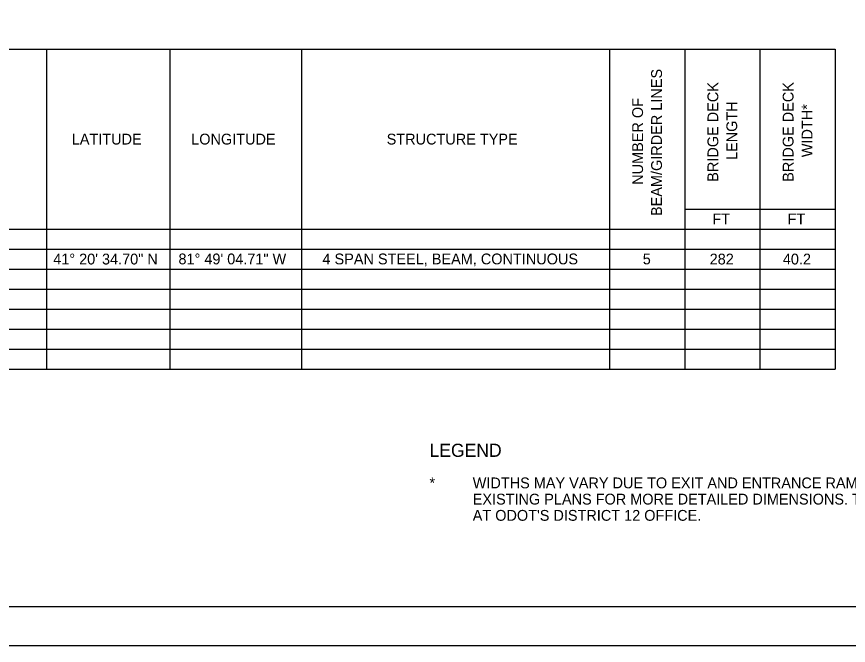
# Model space of a CAD drawing. Extents: x 0 to 680, y 0 to 440.
# Drawn here: x 339 to 554.3, y 0 to 162.7 of the extents above; entities that cross this region are included whole.
import ezdxf

# ---------------------------------------------------------------- set-up
doc = ezdxf.new("R2010")
doc.units = 0
for name, color, linetype in [('DR_P_Text', 7, 'Continuous'), ('SH_Border', 7, 'Continuous'), ('SH_Cut_Line', 7, 'Continuous'), ('SH_Text', 7, 'Continuous')]:
    doc.layers.add(name, color=color, linetype=linetype)

msp = doc.modelspace()

# ---------------------------------------------------------------- linework, layer by layer
at = {"layer": 'SH_Border'}
msp.add_lwpolyline([(30, 430), (670, 430), (670, 10), (30, 10)], close=True, dxfattribs=at)
at = {"layer": 'SH_Cut_Line'}
msp.add_lwpolyline([(0, 0), (680, 0), (680, 440), (0, 440)], close=True, dxfattribs=at)
at = {"layer": 'SH_Text'}
for p, q in [((124.85, 154.3), (550.93, 154.3)), ((346.72, 154.3), (346.72, 71.51)), ((378.67, 154.3), (378.67, 71.51)), ((412.76, 154.3), (412.76, 71.51)), ((492.5, 154.3), (492.5, 71.51)), ((511.98, 154.3), (511.98, 71.51)), ((531.46, 154.3), (531.46, 71.51)), ((550.93, 154.3), (550.93, 71.51)), ((511.98, 112.9), (550.93, 112.9)), ((124.85, 107.73), (550.93, 107.73)), ((124.85, 102.56), (550.93, 102.56)), ((124.85, 97.38), (550.93, 97.38)), ((124.85, 92.21), (550.93, 92.21)), ((124.85, 87.04), (550.93, 87.04)), ((124.85, 81.86), (550.93, 81.86)), ((124.85, 76.69), (550.93, 76.69)), ((124.85, 71.51), (550.93, 71.51))]:
    msp.add_line(p, q, dxfattribs=at)

# ---------------------------------------------------------------- texts
at = {"layer": 'DR_P_Text'}
for s, height, p in [('LEGEND', 3.4, (445.9, 48.78)), ('*', 2.8, (445.9, 40.64)), ('WIDTHS MAY VARY DUE TO EXIT AND ENTRANCE RAMPS ON THE STRUCTURE. SEE', 2.8, (457.1, 40.64)), ('EXISTING PLANS FOR MORE DETAILED DIMENSIONS. THESE PLANS CAN BE VIEWED', 2.8, (457.1, 36.44)), ("AT ODOT'S DISTRICT 12 OFFICE.", 2.8, (457.1, 32.24))]:
    msp.add_text(s, height=height, dxfattribs=at).set_placement(p)
at = {"layer": 'SH_Text'}
for s, p in [('BEAM/GIRDER LINES', (506.09, 111.11)), ('BRIDGE DECK ', (520.67, 119.97)), ('BRIDGE DECK ', (540.15, 119.97)), ('NUMBER OF ', (501.19, 119.18)), ('LENGTH', (525.57, 125.6)), ('WIDTH*', (545.05, 126.33))]:
    msp.add_text(s, height=2.8, rotation=90, dxfattribs=at).set_placement(p)
for s, p in [('LATITUDE', (353.3, 129.61)), ('LONGITUDE', (384.22, 129.61)), ('STRUCTURE TYPE', (434.82, 129.61)), ('FT', (519.13, 108.95)), ('FT', (538.61, 108.95)), ('41° 20\' 34.70" N', (348.5, 98.57)), ('81° 49\' 04.71" W', (380.92, 98.6)), ('4 SPAN STEEL, BEAM, CONTINUOUS', (418.2, 98.6)), ('5', (501.12, 98.6)), ('282', (518.44, 98.57)), ('40.2', (537.38, 98.57))]:
    msp.add_text(s, height=2.8, dxfattribs=at).set_placement(p)

doc.saveas('drawing.dxf')
